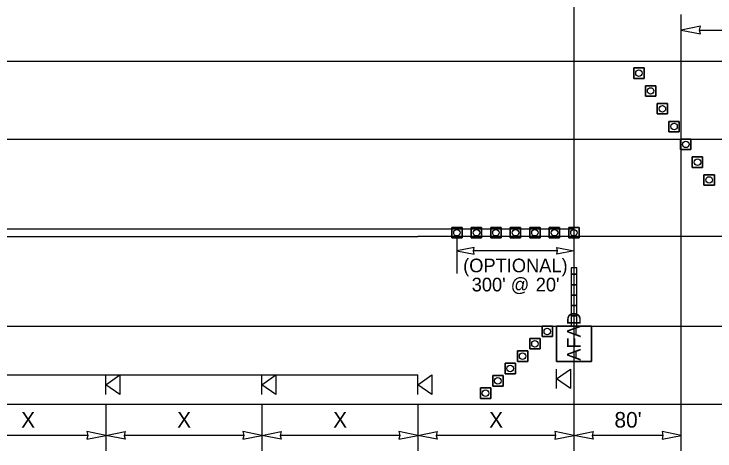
# Model space of a CAD drawing. Extents: x 99999.1 to 100095.7, y 99995 to 100010.7.
# Drawn here: x 100041.405 to 100045, y 100005.492 to 100007.734 of the extents above; entities that cross this region are included whole.
import ezdxf

# ---------------------------------------------------------------- set-up
doc = ezdxf.new("R2010")
doc.units = 0
for name, color, linetype in [('RD_ED_ShoulderPavedEdge', 7, 'Continuous'), ('RD_MK_LineDblYellowCenter', 7, 'Continuous'), ('RD_MK_LineEdgeWhite', 7, 'Continuous'), ('RD_MK_LineNoPass', 7, 'Continuous'), ('RD_MK_LineSkipCenter', 7, 'Continuous'), ('TR_WZ_AFAD', 7, 'Continuous'), ('TR_WZ_PortableSignMountBlk-Org', 7, 'Continuous'), ('TR_WZ_PortableSignMountBlk-Wht', 7, 'Continuous'), ('TR_WZ_TrafficCone', 7, 'Continuous'), ('TR_WZ_WorkZoneDetails', 7, 'Continuous'), ('TR_WZ_WorkZoneTextCurrent', 7, 'Continuous')]:
    doc.layers.add(name, color=color, linetype=linetype)

msp = doc.modelspace()

# ---------------------------------------------------------------- linework, layer by layer
at = {"layer": 'RD_ED_ShoulderPavedEdge'}
for p, q in [((100040.1076, 100007.4923), (100055.6424, 100007.4923)), ((100040.1076, 100005.7323), (100055.6424, 100005.7323))]:
    msp.add_line(p, q, dxfattribs=at)
at = {"layer": 'RD_MK_LineDblYellowCenter'}
for p, q in [((100040.1282, 100006.6323), (100043.4767, 100006.6323)), ((100040.0869, 100006.5923), (100043.4767, 100006.5923))]:
    msp.add_line(p, q, dxfattribs=at)
at = {"layer": 'RD_MK_LineEdgeWhite'}
for p, q in [((100040.1076, 100007.0923), (100055.6424, 100007.0923)), ((100040.1076, 100006.1323), (100055.6424, 100006.1323))]:
    msp.add_line(p, q, dxfattribs=at)
at = {"layer": 'RD_MK_LineNoPass'}
msp.add_line((100043.4767, 100006.6323), (100044.2767, 100006.6323), dxfattribs=at)
at = {"layer": 'RD_MK_LineSkipCenter'}
msp.add_lwpolyline([(100051.15, 100006.5923), (100043.4767, 100006.5923)], dxfattribs=at)
at = {"layer": 'TR_WZ_AFAD'}
for p, q in [((100044.2916, 100006.399), (100044.2916, 100006.4323)), ((100044.2616, 100006.399), (100044.2616, 100006.3457)), ((100044.2616, 100006.399), (100044.2766, 100006.399)), ((100044.2766, 100006.399), (100044.2916, 100006.399)), ((100044.2916, 100006.3457), (100044.2916, 100006.399)), ((100044.2616, 100006.3457), (100044.2616, 100006.2923)), ((100044.2766, 100006.3457), (100044.2616, 100006.3457)), ((100044.2916, 100006.3457), (100044.2766, 100006.3457)), ((100044.2916, 100006.2923), (100044.2916, 100006.3457)), ((100044.2616, 100006.2923), (100044.2616, 100006.239)), ((100044.2616, 100006.2923), (100044.2766, 100006.2923)), ((100044.2766, 100006.2923), (100044.2916, 100006.2923)), ((100044.2916, 100006.239), (100044.2916, 100006.2923)), ((100044.2766, 100006.239), (100044.2616, 100006.239)), ((100044.2616, 100006.239), (100044.2616, 100006.1857)), ((100044.2916, 100006.239), (100044.2766, 100006.239)), ((100044.2916, 100006.1857), (100044.2916, 100006.239)), ((100044.2616, 100006.1857), (100044.2616, 100006.1323)), ((100044.1866, 100005.9523), (100044.1866, 100006.1323)), ((100044.1866, 100006.1323), (100044.3666, 100006.1323)), ((100044.27, 100006.1323), (100044.1866, 100006.1323)), ((100044.1866, 100006.1323), (100044.1866, 100005.9523)), ((100044.2616, 100006.1323), (100044.27, 100006.1323)), ((100044.27, 100006.1323), (100044.2766, 100006.1323)), ((100044.3666, 100006.1323), (100044.3666, 100005.9523)), ((100044.3666, 100005.9523), (100044.3666, 100006.1323)), ((100044.3666, 100005.9523), (100044.1866, 100005.9523)), ((100044.1866, 100005.9523), (100044.3666, 100005.9523))]:
    msp.add_line(p, q, dxfattribs=at)
for points in [[(100044.2916, 100006.4323), (100044.2616, 100006.4323), (100044.2616, 100006.399)], [(100044.2916, 100006.1323), (100044.2916, 100006.4323), (100044.2616, 100006.4323), (100044.2616, 100006.1323)], [(100044.2916, 100006.399), (100044.2766, 100006.399), (100044.2616, 100006.399)], [(100044.2616, 100006.3457), (100044.2766, 100006.3457), (100044.2916, 100006.3457)], [(100044.2916, 100006.2923), (100044.2766, 100006.2923), (100044.2616, 100006.2923)], [(100044.2616, 100006.239), (100044.2766, 100006.239), (100044.2916, 100006.239)], [(100044.2916, 100006.1857), (100044.2766, 100006.1857), (100044.2616, 100006.1857)], [(100044.2616, 100006.1857), (100044.2766, 100006.1857), (100044.2916, 100006.1857)], [(100044.2766, 100006.1323), (100044.2833, 100006.1323), (100044.2916, 100006.1323), (100044.2916, 100006.1857)], [(100044.3666, 100006.1323), (100044.2833, 100006.1323), (100044.27, 100006.1323)]]:
    msp.add_lwpolyline(points, dxfattribs=at)
at = {"layer": 'TR_WZ_PortableSignMountBlk-Org'}
for p, q in [((100041.8767, 100005.7824), (100041.8767, 100005.8824)), ((100042.6767, 100005.7824), (100042.6767, 100005.8824)), ((100043.4767, 100005.7824), (100043.4767, 100005.8824))]:
    msp.add_line(p, q, dxfattribs=at)
for points in [[(100041.8767, 100005.8323), (100041.9485, 100005.8824), (100041.9485, 100005.7824)], [(100042.6767, 100005.8323), (100042.7485, 100005.8824), (100042.7485, 100005.7824)], [(100043.4767, 100005.8323), (100043.5485, 100005.8824), (100043.5485, 100005.7824)]]:
    msp.add_lwpolyline(points, close=True, dxfattribs=at)
at = {"layer": 'TR_WZ_PortableSignMountBlk-Wht'}
msp.add_line((100044.1867, 100005.8123), (100044.1867, 100005.9123), dxfattribs=at)
msp.add_lwpolyline([(100044.1867, 100005.8622), (100044.2585, 100005.9123), (100044.2585, 100005.8123)], close=True, dxfattribs=at)
at = {"layer": 'TR_WZ_TrafficCone'}
for points in [[(100044.6367, 100007.4577), (100044.5834, 100007.4577), (100044.5834, 100007.4043), (100044.6367, 100007.4043), (100044.6367, 100007.4577)], [(100044.6367, 100007.4043), (100044.5834, 100007.4043), (100044.5834, 100007.4577), (100044.6367, 100007.4577), (100044.6367, 100007.4043)], [(100044.6967, 100007.3663), (100044.6434, 100007.3663), (100044.6434, 100007.313), (100044.6967, 100007.313), (100044.6967, 100007.3663)], [(100044.6967, 100007.313), (100044.6434, 100007.313), (100044.6434, 100007.3663), (100044.6967, 100007.3663), (100044.6967, 100007.313)], [(100044.7567, 100007.275), (100044.7034, 100007.275), (100044.7034, 100007.2217), (100044.7567, 100007.2217), (100044.7567, 100007.275)], [(100044.7567, 100007.2217), (100044.7034, 100007.2217), (100044.7034, 100007.275), (100044.7567, 100007.275), (100044.7567, 100007.2217)], [(100044.8167, 100007.1837), (100044.7634, 100007.1837), (100044.7634, 100007.1303), (100044.8167, 100007.1303), (100044.8167, 100007.1837)], [(100044.8167, 100007.1303), (100044.7634, 100007.1303), (100044.7634, 100007.1837), (100044.8167, 100007.1837), (100044.8167, 100007.1303)], [(100044.8234, 100007.0923), (100044.8767, 100007.0923), (100044.8767, 100007.039), (100044.8234, 100007.039), (100044.8234, 100007.0923)], [(100044.8234, 100007.039), (100044.8767, 100007.039), (100044.8767, 100007.0923), (100044.8234, 100007.0923), (100044.8234, 100007.039)], [(100044.8834, 100007.001), (100044.9367, 100007.001), (100044.9367, 100006.9477), (100044.8834, 100006.9477), (100044.8834, 100007.001)], [(100044.8834, 100006.9477), (100044.9367, 100006.9477), (100044.9367, 100007.001), (100044.8834, 100007.001), (100044.8834, 100006.9477)], [(100044.9434, 100006.9097), (100044.9967, 100006.9097), (100044.9967, 100006.8563), (100044.9434, 100006.8563), (100044.9434, 100006.9097)], [(100044.9434, 100006.8563), (100044.9967, 100006.8563), (100044.9967, 100006.9097), (100044.9434, 100006.9097), (100044.9434, 100006.8563)], [(100043.7033, 100006.639), (100043.65, 100006.639), (100043.65, 100006.5857), (100043.7033, 100006.5857), (100043.7033, 100006.639)], [(100043.7033, 100006.5857), (100043.65, 100006.5857), (100043.65, 100006.639), (100043.7033, 100006.639), (100043.7033, 100006.5857)], [(100043.8033, 100006.639), (100043.75, 100006.639), (100043.75, 100006.5857), (100043.8033, 100006.5857), (100043.8033, 100006.639)], [(100043.8033, 100006.5857), (100043.75, 100006.5857), (100043.75, 100006.639), (100043.8033, 100006.639), (100043.8033, 100006.5857)], [(100043.9033, 100006.639), (100043.85, 100006.639), (100043.85, 100006.5857), (100043.9033, 100006.5857), (100043.9033, 100006.639)], [(100043.9033, 100006.5857), (100043.85, 100006.5857), (100043.85, 100006.639), (100043.9033, 100006.639), (100043.9033, 100006.5857)], [(100044.0033, 100006.639), (100043.95, 100006.639), (100043.95, 100006.5857), (100044.0033, 100006.5857), (100044.0033, 100006.639)], [(100044.0033, 100006.5857), (100043.95, 100006.5857), (100043.95, 100006.639), (100044.0033, 100006.639), (100044.0033, 100006.5857)], [(100044.1033, 100006.639), (100044.05, 100006.639), (100044.05, 100006.5857), (100044.1033, 100006.5857), (100044.1033, 100006.639)], [(100044.1033, 100006.5857), (100044.05, 100006.5857), (100044.05, 100006.639), (100044.1033, 100006.639), (100044.1033, 100006.5857)], [(100044.2033, 100006.639), (100044.15, 100006.639), (100044.15, 100006.5857), (100044.2033, 100006.5857), (100044.2033, 100006.639)], [(100044.2033, 100006.5857), (100044.15, 100006.5857), (100044.15, 100006.639), (100044.2033, 100006.639), (100044.2033, 100006.5857)], [(100044.3033, 100006.639), (100044.25, 100006.639), (100044.25, 100006.5857), (100044.3033, 100006.5857), (100044.3033, 100006.639)], [(100044.3033, 100006.5857), (100044.25, 100006.5857), (100044.25, 100006.639), (100044.3033, 100006.639), (100044.3033, 100006.5857)], [(100044.1133, 100006.1323), (100044.1667, 100006.1323), (100044.1667, 100006.079), (100044.1133, 100006.079), (100044.1133, 100006.1323)], [(100044.1133, 100006.079), (100044.1667, 100006.079), (100044.1667, 100006.1323), (100044.1133, 100006.1323), (100044.1133, 100006.079)], [(100044.05, 100006.069), (100044.1033, 100006.069), (100044.1033, 100006.0157), (100044.05, 100006.0157), (100044.05, 100006.069)], [(100044.05, 100006.0157), (100044.1033, 100006.0157), (100044.1033, 100006.069), (100044.05, 100006.069), (100044.05, 100006.0157)], [(100043.9867, 100006.0057), (100044.04, 100006.0057), (100044.04, 100005.9523), (100043.9867, 100005.9523), (100043.9867, 100006.0057)], [(100043.9867, 100005.9523), (100044.04, 100005.9523), (100044.04, 100006.0057), (100043.9867, 100006.0057), (100043.9867, 100005.9523)], [(100043.9767, 100005.9423), (100043.9233, 100005.9423), (100043.9233, 100005.889), (100043.9767, 100005.889), (100043.9767, 100005.9423)], [(100043.9767, 100005.889), (100043.9233, 100005.889), (100043.9233, 100005.9423), (100043.9767, 100005.9423), (100043.9767, 100005.889)], [(100043.9133, 100005.879), (100043.86, 100005.879), (100043.86, 100005.8257), (100043.9133, 100005.8257), (100043.9133, 100005.879)], [(100043.9133, 100005.8257), (100043.86, 100005.8257), (100043.86, 100005.879), (100043.9133, 100005.879), (100043.9133, 100005.8257)], [(100043.85, 100005.8157), (100043.7967, 100005.8157), (100043.7967, 100005.7623), (100043.85, 100005.7623), (100043.85, 100005.8157)], [(100043.85, 100005.7623), (100043.7967, 100005.7623), (100043.7967, 100005.8157), (100043.85, 100005.8157), (100043.85, 100005.7623)]]:
    msp.add_lwpolyline(points, dxfattribs=at)
for centre in [(100044.61, 100007.431), (100044.67, 100007.3397), (100044.73, 100007.2483), (100044.79, 100007.157), (100044.85, 100007.0657), (100044.91, 100006.9743), (100044.97, 100006.883), (100043.6767, 100006.6123), (100043.7767, 100006.6123), (100043.8767, 100006.6123), (100043.9767, 100006.6123), (100044.0767, 100006.6123), (100044.1767, 100006.6123), (100044.2767, 100006.6123), (100044.14, 100006.1057), (100044.0767, 100006.0423), (100044.0133, 100005.979), (100043.95, 100005.9157), (100043.8867, 100005.8523), (100043.8233, 100005.789)]:
    msp.add_circle(centre, 0.0167, dxfattribs=at)
at = {"layer": 'TR_WZ_WorkZoneDetails'}
for p, q in [((100044.2767, 100008.7991), (100044.2767, 100005.4923)), ((100044.8267, 100005.4923), (100044.8267, 100007.7323)), ((100044.9204, 100007.6523), (100045.0563, 100007.6523)), ((100043.6767, 100006.5857), (100043.6767, 100006.4023)), ((100044.1923, 100006.5193), (100043.761, 100006.5193)), ((100041.0767, 100005.8824), (100043.4767, 100005.8824)), ((100041.8767, 100005.7323), (100041.8767, 100005.4923)), ((100042.6767, 100005.7323), (100042.6767, 100005.4923)), ((100043.4767, 100005.7323), (100043.4767, 100005.4923)), ((100041.7829, 100005.5723), (100041.1704, 100005.5723)), ((100042.5829, 100005.5723), (100041.9704, 100005.5723)), ((100043.3829, 100005.5723), (100042.7704, 100005.5723)), ((100044.1829, 100005.5723), (100043.5704, 100005.5723)), ((100044.7329, 100005.5723), (100044.3704, 100005.5723))]:
    msp.add_line(p, q, dxfattribs=at)
for points in [[(100044.8267, 100007.6523), (100044.9249, 100007.6331), (100044.9204, 100007.6523), (100044.9249, 100007.6716)], [(100043.6767, 100006.5193), (100043.7651, 100006.502), (100043.761, 100006.5193), (100043.7651, 100006.5367)], [(100044.2767, 100006.5193), (100044.1882, 100006.502), (100044.1923, 100006.5193), (100044.1882, 100006.5367)], [(100041.8767, 100005.5723), (100041.7784, 100005.5916), (100041.7829, 100005.5723), (100041.7784, 100005.5531)], [(100041.8767, 100005.5723), (100041.9749, 100005.5916), (100041.9704, 100005.5723), (100041.9749, 100005.5531)], [(100042.6767, 100005.5723), (100042.5784, 100005.5916), (100042.5829, 100005.5723), (100042.5784, 100005.5531)], [(100042.6767, 100005.5723), (100042.7749, 100005.5916), (100042.7704, 100005.5723), (100042.7749, 100005.5531)], [(100043.4767, 100005.5723), (100043.3784, 100005.5916), (100043.3829, 100005.5723), (100043.3784, 100005.5531)], [(100043.4767, 100005.5723), (100043.5749, 100005.5916), (100043.5704, 100005.5723), (100043.5749, 100005.5531)], [(100044.2767, 100005.5723), (100044.1784, 100005.5916), (100044.1829, 100005.5723), (100044.1784, 100005.5531)], [(100044.2767, 100005.5723), (100044.3749, 100005.5916), (100044.3704, 100005.5723), (100044.3749, 100005.5531)], [(100044.8267, 100005.5723), (100044.7284, 100005.5916), (100044.7329, 100005.5723), (100044.7284, 100005.5531)]]:
    msp.add_lwpolyline(points, close=True, dxfattribs=at)

# ---------------------------------------------------------------- texts
at = {"layer": 'TR_WZ_AFAD'}
msp.add_text('AFAD', height=0.07, rotation=90, dxfattribs=at).set_placement((100044.3116, 100005.9553))
at = {"layer": 'TR_WZ_WorkZoneTextCurrent'}
for s, p in [('(OPTIONAL)', (100043.7085, 100006.4093)), ("300' @", (100043.7523, 100006.3113)), ("20'", (100044.0807, 100006.3113))]:
    msp.add_text(s, height=0.07, dxfattribs=at).set_placement(p)
for s, p in [('X', (100041.4419, 100005.6123)), ('X', (100042.2419, 100005.6123)), ('X', (100043.0419, 100005.6123)), ('X', (100043.8419, 100005.6123)), ("80'", (100044.4844, 100005.6123))]:
    msp.add_text(s, height=0.08, rotation=360, dxfattribs=at).set_placement(p)

doc.saveas('drawing.dxf')
